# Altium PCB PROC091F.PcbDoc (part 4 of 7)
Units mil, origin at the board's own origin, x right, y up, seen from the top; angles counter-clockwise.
Board outline 3590.95 x 906.17 mil, 8 copper layers (Top Layer, GND1, Sig1, PWR1, PWR2, Sig2, GND2, Bottom Layer), stack 63.146 mil thick; 420 components, 316 nets, 1432 pads, 774 vias.
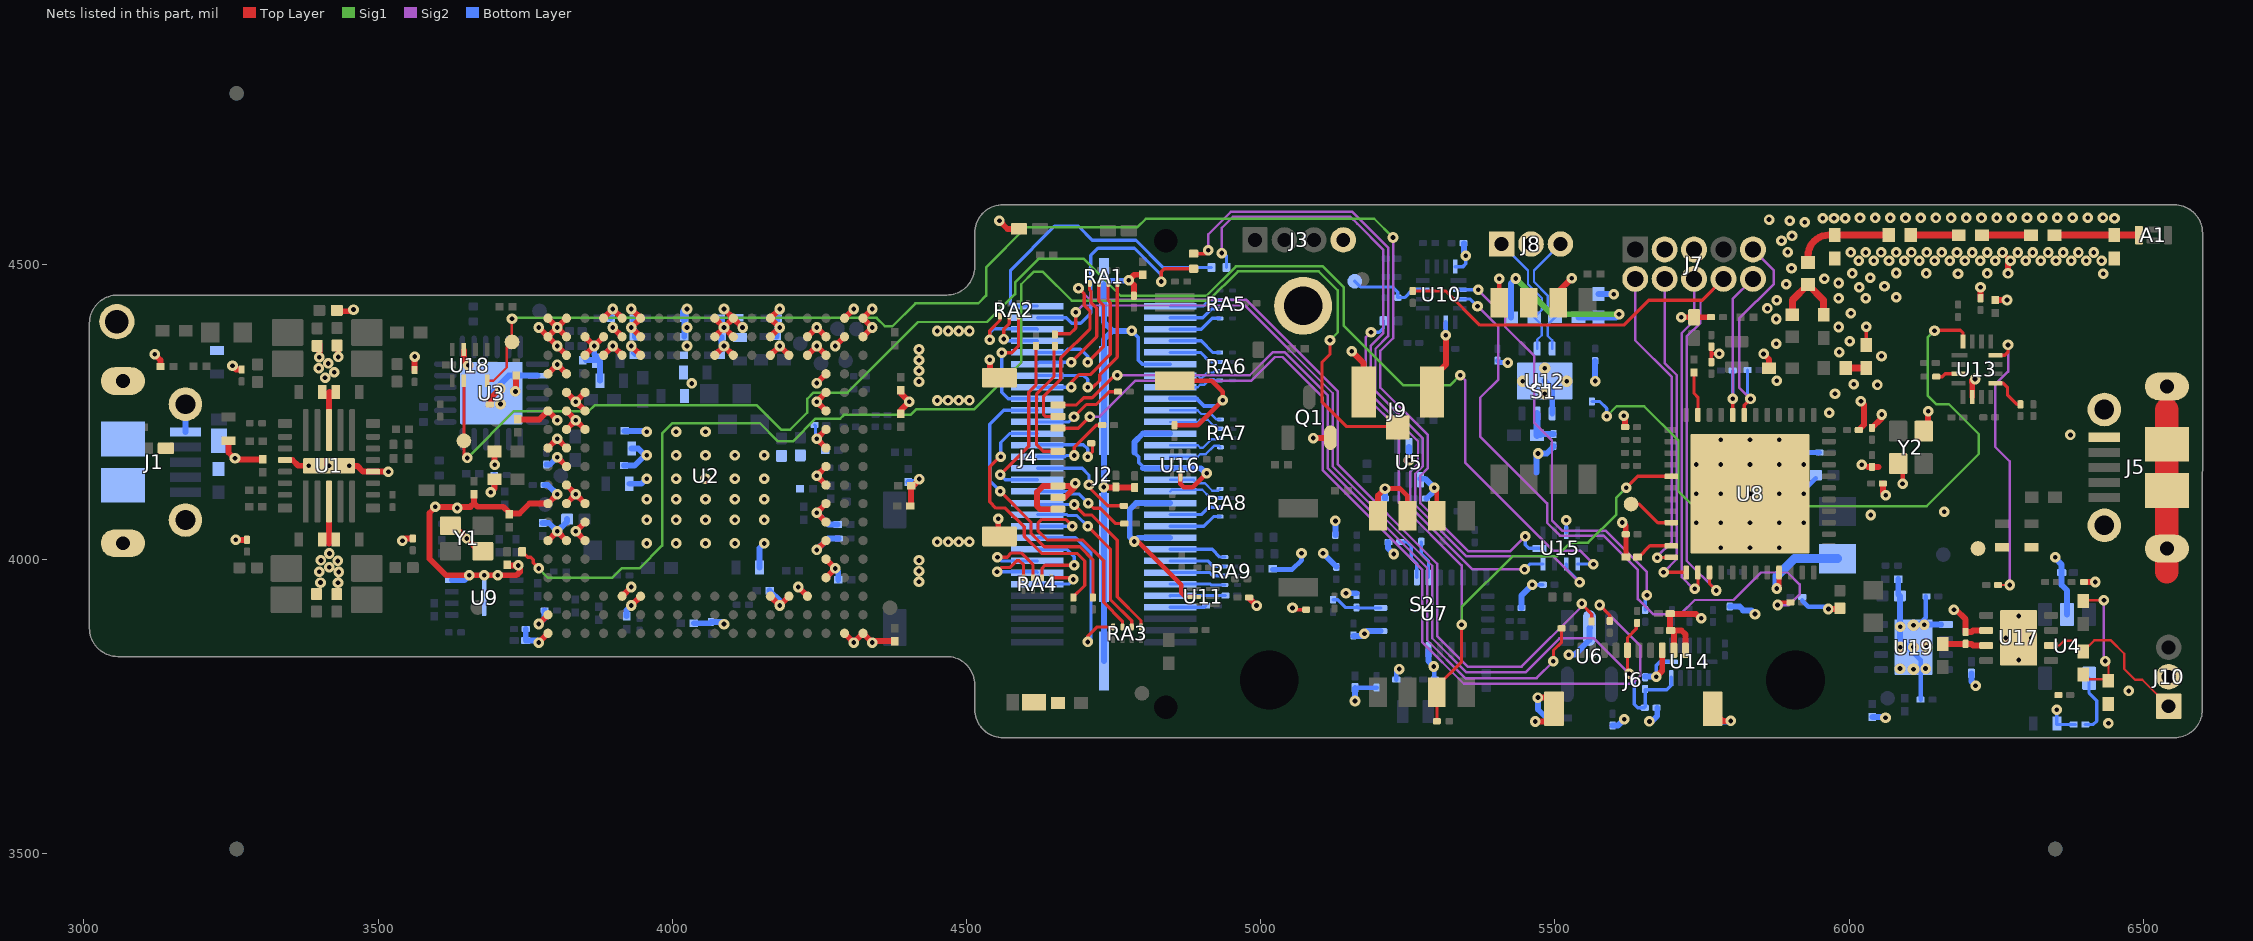
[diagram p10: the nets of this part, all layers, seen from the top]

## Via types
v1: diameter 18, hole 8, Top Layer to Bottom Layer, tented both sides, 737 vias
v2: diameter 19.68, hole 7.87, Top Layer to Bottom Layer, tented both sides, 36 vias
v3: diameter 17, hole 8, Top Layer to Bottom Layer, tented both sides, 1 vias

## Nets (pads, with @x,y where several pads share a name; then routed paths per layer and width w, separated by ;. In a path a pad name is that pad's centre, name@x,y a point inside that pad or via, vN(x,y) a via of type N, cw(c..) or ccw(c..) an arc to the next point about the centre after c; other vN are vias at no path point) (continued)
BOOTN: R80.2 R96.1 U7.4 | length 89.9
  Bottom Layer w5.5: R80.2@5123,3931 5130.87,3931 5142.87,3919 5143,3919 ; 5142,3920 5143,3919 ; R96.1@5162.8,3917.57 5144.43,3917.57 5143,3919 ; R96.1@5162.8,3919 R96.1@5163.76,3919 ; R96.1@5165,3919 R96.1@5163.76,3919 ; U7.4@5203.84,3917.06 5165.69,3917.06 R96.1@5163.76,3919
BREAK_RS232RX: TP19.1 U15.6 U18.7 | length 2663.5
  Top Layer w5.5: U18.7@3645.95,4303.01 TP19.1@3645.95,4200.94 3645.95,4177.64 v1(3651.7,4171.89)
  Sig1 w4.2: v1(3651.7,4171.89) 3651.8,4171.89 3731.31,4251.4 3858.11,4251.4 3867.87,4261.15 4143.84,4261.15 4184.81,4220.18 4200.56,4220.18 4229.37,4248.99 4229.37,4272.16 4240.11,4282.89 4297.89,4282.89 4417.91,4402.91 4534.91,4402.91 4582.46,4450.46 4582.46,4470.35 4622.27,4510.16 4699.37,4510.16 4761.92,4447.6 4908.02,4447.6 4957.82,4497.4 5105.6,4497.4 5141.34,4461.66 5141.34,4396.41 5242.09,4295.66 5322.29,4295.66 v1(5339,4312.38)
  Sig2 w4.2: v1(5339,4312.38) 5347.73,4303.65 5347.73,4248.79 ; 5347.71,4215.22 5347.71,4248.78 ; 5347.73,4215.21 5347.73,4163.41 5496.63,4014.5 5542.33,4014.5 v1(5565.37,3991.46)
  Bottom Layer w5.5: U15.6@5538.73,3991.77 5539.04,3991.46 v1(5565.37,3991.46)
BREAK_RS232TX: TP18.1 U15.10 U18.9 | length 2513.4
  Top Layer w4.2: U18.9@3685.32,4303.01 3695.92,4303.01 3718.72,4325.81 3718.72,4360.18 TP18.1@3727.56,4369.01 v1@3727.56,4409.77
  Sig1 w4.2: v1@3727.56,4409.77 4347.13,4409.77 4361.3,4395.61 4373.97,4395.61 4413.02,4434.66 4519.99,4434.66 4533.24,4447.91 4533.24,4495.82 4601.57,4564.15 4790.54,4564.15 4804.73,4578.34 5192.99,4578.34 v1(5224.85,4546.48)
  Sig2 w4.2: v1(5224.85,4546.48) 5224.85,4375.38 5203.48,4354.01 5203.48,4291.19 5284.08,4210.6 5284.08,4154.51 5271.03,4141.47 5271.03,4095.28 5353.32,4012.99 5423.87,4012.99 v1(5449.37,4038.49)
  Bottom Layer w5.5: v1(5449.37,4038.49) 5449.37,4024.34 5455.37,4018.34 U15.10@5473.77,4018.34
  other v1: 3727.56,4408.57
"BT ENABLE": R30.1 R110.1 S2.3 U8.17 | length 1280.9
  Top Layer w5.5: R110.1@5299.37,3724.46 S2.3@5299.37,3773.46 5299.37,3783.46 5341.37,3825.46 v1(5341.37,3888.46) ; v1(5621,4121) 5640.64,4140.64 U8.17@5697.71,4140.64
  Sig1 w4.2: v1(5341.37,3888.46) 5341.37,3918.37 5427.68,4004.68 5502.99,4004.68 5526.3,4028 5556.37,4028 5604.37,4076 5604.37,4104.37 v1(5621,4121)
  Sig2 w4.2: v1(5187.37,4385.46) 5178.28,4376.37 5178.28,4276.72 5234.87,4220.13 5234.87,4095.8 5341.37,3989.3 v1(5341.37,3888.46)
  Bottom Layer w5.5: v1(5187.37,4385.46) 5201.11,4385.46 5208.7,4393.06 R30.1@5208.7,4404.87
BT_RST: R91.2 U10.3 | length 1123.3
  Top Layer w5.5: v1(5878.37,3921.94) 5882.89,3926.46 R91.2@5900.13,3926.46
  Sig2 w4.2: v1(5368.37,4429.85) 5403.87,4394.36 5403.87,4305.15 5372.93,4274.2 5372.93,4238.35 ; 5372.91,4225.66 5372.91,4238.34 ; 5372.93,4225.65 5372.93,4208.47 5486.6,4094.79 5486.6,4061.8 5508.4,4040 5582.47,4040 5641.07,3981.4 5641.07,3932.13 5666.73,3906.46 5713.69,3906.46 5737.69,3930.46 5803.46,3930.46 5850.2,3977.2 5895.63,3977.2 5915.77,3957.07 5915.77,3939.99 5897.72,3921.94 v1(5878.37,3921.94)
  Bottom Layer w5.5: U10.3@5338.3,4441.85 5356.37,4441.85 v1(5368.37,4429.85)
BT_UART_RX: J7.9 R90.2 U8.7 | length 384
  Top Layer w5.5: U8.7@5821.73,4244.97 5821.76,4245 5821.76,4261.53 v1(5832.37,4272.14)
  Sig2 w4.2: v1(5832.37,4272.14) 5813,4291.51 5813,4408.67 5872,4467.67 5872,4490.65 J7.9@5836.47,4526.19
  Bottom Layer w5.5: R90.2@5827.38,4321.29 5827.38,4277.13 v1(5832.37,4272.14)
BT_UART_TX: J7.10 R102.2 U8.8 | length 293.4
  Top Layer w5.5: U8.8@5802.04,4244.97 v1(5802.04,4272.45)
  Sig2 w4.2: v1(5802.04,4272.45) 5802.04,4441.76 J7.10@5836.47,4476.19
  Bottom Layer w5.5: v1(5802.04,4272.45) R102.2@5802.04,4320.41
CAN1_FD_RX: R127.2 U13.3 | length 39.7
  Top Layer w5.5: R127.2@6148,4310 6158.12,4310 6163,4314.88 U13.3@6185.63,4314.88
CAN1_FD_TX: R123.2 U13.16 | length 1168.2
  Top Layer w5.5: v1(6145,4388) 6146,4389 6189,4389 6193.5,4384.5 U13.16@6193.5,4370
  Sig1 w4.2: v1(5588,4242.75) 5604.92,4259.66 5651.61,4259.66 5710,4201.27 5710,4115 5735,4090 5992.27,4090 5992.45,4090.18 6131.82,4090.18 6220.3,4178.66 6220.3,4212.34 6169.34,4263.3 6147.7,4263.3 6133.3,4277.7 6133.3,4376.3 v1(6145,4388)
  Bottom Layer w5.5: R123.2@5563,4267.77 5576.23,4267.77 5588,4256 v1(5588,4242.75)
CAN2_FD_RX: R120.2 U13.9 | length 65
  Top Layer w5.5: U13.9@6248.62,4299.13 6262,4299.13 6269,4292.13 6269,4279.1 6285.1,4263 R120.2@6291,4263
CAN2_FD_TX: R116.2 U13.12 | length 483.1
  Top Layer w4: R116.2@6252.99,3956 v1(6272.97,3956)
  Top Layer w5.5: U13.12@6248.62,4346.38 6264.28,4346.38 6270,4352.1 v1(6270,4364)
  Sig2 w4.2: v1(6270,4364) 6270,4318.7 6248,4296.7 6248,4191 6272.97,4166.03 v1(6272.97,3956)
CLKSEL0: R82.2 U7.10 | length 65.5
  Bottom Layer w5.5: R82.2@5272.85,4029.17 5272.85,4009.38 5285.04,3997.19 U7.10@5285.04,3968.74
CONN_AR_RS232RX: R14.2 U15.7 | length 1259.6
  Top Layer w5.5: R14.2@4886,4519.05 4906.72,4519.05 v1@4911,4523.33
  Sig2 w4.2: v1(4911,4525) 4911,4551.96 4949.04,4590 5155.96,4590 5216.44,4529.52 5216.44,4378.86 5195.08,4357.49 5195.08,4285.49 5275.68,4204.89 5275.68,4157.99 5262.63,4144.95 5262.63,4091.8 5349.84,4004.59 5497.75,4004.59 v1(5541.83,3960.5)
  Bottom Layer w5.5: U15.7@5519.05,3991.77 5519.05,3983.29 v1(5541.83,3960.5)
CONN_AR_RS232TX: R12.2 U15.9 | length 1135.8
  Sig2 w4.2: v1(4934,4520) 4934,4563.08 4952.46,4581.54 5152.55,4581.54 5164.08,4570 5208.05,4526.04 5208.05,4383.58 5186.68,4362.22 5186.68,4280.81 5267.28,4200.22 5267.28,4161.47 5254.23,4148.43 5254.23,4088.32 5360.12,3982.44 v1(5448.37,3982.44)
  Bottom Layer w5.5: v1(4934,4520) 4936.91,4520 4941.96,4514.95 R12.2@4941.96,4495.46 ; v1(5448.37,3982.44) 5457.7,3991.77 U15.9@5479.68,3991.77
DCDC_SW: L7.1 U8.33 | length 165.6
  Top Layer w8: v1(5876.87,3950) 5880.78,3953.91 U8.33@5880.78,3977.25
  Bottom Layer w15: v1(5876.87,3950) 5876.87,3971.1 5906.6,4000.83 L7.1@5980.15,4000.83
DIO6_GLED: R17.1 U8.11 | length 74.9
  Top Layer w5.5: R17.1@5736.37,4317.15 5736.37,4281.63 5742.99,4275.01 U8.11@5742.99,4244.97
DISP: R168.2 U10.2 | length 739.6
  Sig2 w4.2: v1(5369.57,4457.6) 5415.3,4411.87 5415.3,4394.81 5465,4345.11 5465,4231.46 5495,4201.46 5495,4065.5 5512.1,4048.4 5585.95,4048.4 5656.37,3977.98 v1(5656.37,3938.46)
  Bottom Layer w5.5: U10.2@5337.31,4457.6 v1(5369.57,4457.6) ; R168.2@5653.43,3913.58 5653.43,3935.52 v1(5656.37,3938.46)
DISP_T: C114.2 J6.5 R180.2 R181.1 R182.1 U14.5 | length 1724.1
  Top Layer w5.5: R182.1@4650.14,4382.85 4675.87,4382.85 4685.68,4392.66 v1(4685.68,4419.55) ; v1(5626.13,3805.38) 5623.32,3808.19 J6.5@5623.32,3845.06 5623.32,3866.63 5638.29,3881.6 R181.1@5638.29,3890.63
  Sig2 w4.2: v1(4685.68,4419.55) 4697.08,4430.95 4973.3,4430.95 5122.43,4281.83 5122.43,4157.66 5291.47,3988.61 5291.47,3865.5 5349.4,3807.57 5449.92,3807.57 5507.5,3865.15 5566.37,3865.15 v1(5626.13,3805.38)
  Bottom Layer w5.5: v1(5626.13,3805.38) 5634.82,3796.69 5634.82,3753.22 5640.7,3747.34 5651.73,3747.34 5653.37,3748.99 5653.37,3778.13 5690.11,3778.13 5697.73,3785.75 U14.5@5697.73,3797.8 U14.5@5697.73,3799.77
GND: C1.1 C2.1 C3.1 C4.2 C5.2 C6.1 C7.2 C8.2 C9.1 C10.1 C11.2 C12.1 C13.1 C14.1 C15.2 C16.2 C17.2 C18.2 C19.2 C20.2 C21.1 C23.2 C24.2 C25.2 C26.2 C27.2 C28.2 C29.2 C30.2 C31.2 C32.2 C33.2 C34.2 C35.2 C36.2 C37.2 C38.2 C39.2 C40.2 C41.2 C42.1 C43.1 C44.2 C45.2 C46.2 C47.2 C48.2 C49.2 C50.2 C51.2 C52.2 C53.2 C54.2 C55.2 C56.2 C57.2 C58.2 C59.2 C60.2 C61.2 C62.2 C63.2 C64.2 C65.2 C66.2 C67.2 C68.2 C69.2 C70.2 C71.1 C72.1 C73.2 C74.2 C75.2 C76.2 C77.2 C78.2 C79.2 C80.2 C81.2 C82.2 C83.2 C84.2 C85.2 C86.2 C87.2 C88.2 C89.2 C90.2 C91.2 C92.2 C94.2 C95.2 C96.2 C97.2 C98.2 C100.2 C101.2 C102.2 C103.2 C104.2 C105.1 C106.1 C107.2 C108.1 C109.1 C110.1 C114.1 C115.2 C116.2 C117.2 C118.2 C119.2 C120.2 C122.2 C123.2 C125.2 C126.2 C127.2 C128.2 C129.2 C130.2 J1.5 J1.6 J1.7 J1.8 J1.9 J1.10 J1.11 J2.20 J2.26 J2.32 J2.38 J2.44 J2.50 J2.MP1 J2.MP2 J2.MP3 J2.MP4 J3.4 J4.8 J4.9 J4.10 J4.11 J4.12 J5.5 J5.6 J5.7 J5.8 J5.9 J5.10 J5.11 J6.8 J6.9 J6.10 J6.11 J6.12 J7.3 J7.5 J8.2 J9.2@5174.89,4283.6 J9.3@5291.03,4283.6 J10.2 LD1.2 LD2.2 LD6.2 Q1.2 R3.2 R15.1 R24.1 R29.1 R37.1 R42.2 R52.1 R65.1 R69.1 R73.1 R92.2 R93.2 R96.2 R98.2 R122.2 R125.1 R134.2 R141.2 R158.1 R170.1 R172.1 R180.1 S1.6 S1.7 S1.8 S2.6 S2.7 S2.8 SW2.2 TP12.1 TP15.1 TP20.1 U1.4 U1.11 U1.17 U1.24 U1.27 U2.A1 U2.A2 U2.A6 U2.A8 U2.A11 U2.A13 U2.A15 U2.A17 U2.A18 U2.B6 U2.B8 U2.B9 U2.B10 U2.B11 U2.B12 U2.B13 U2.B14 U2.B15 U2.B16 U2.B17 U2.B18 U2.C6 U2.C7 U2.C8 U2.C12 U2.C13 U2.C14 U2.C16 U2.C17 U2.D16 U2.D17 U2.D18 U2.E3 U2.E16 U2.E17 U2.E18 U2.F3 U2.F16 U2.F17 U2.F18 U2.K16 U2.K17 U2.K18 U2.L16 U2.L17 U2.L18 U2.N3 U2.N16 U2.N17 U2.N18 U2.P3 U2.P16 U2.R3 U2.R16 U2.R17 U2.T4 U2.T5 U2.T6 U2.T7 U2.T8 U2.T9 U2.T10 U2.T11 U2.T12 U2.T13 U2.T14 U2.T15 U2.T16 U2.T17 U2.U1 U2.U17 U2.U18 U2.V1 U2.V17 U2.V18 U3.2 U3.25 U4.2 U5.2 U5.4 U6.2 U7.2 U7.25 U8.49 U9.4 U9.9 U10.6 U10.16 U11.2 U12.2 U12.9@5482.58,4302.51 U13.6 U14.6 U15.3 U16.2 U17.2 U17.9@6287.97,3866 U18.3 U19.5 U19.9@6109.37,3850.46 Y1.2 Y1.4 Y2.2 Y2.4 | length 10328
  Top Layer w5.5: C40.2@4980.39,3933.61 C40.2@4980.39,3934.38 ; v1(5054,3917) 5056.96,3914.04 R125.1@5077.13,3914.04 ; C20.2@5765.79,4334.83 5765.79,4349 ; C19.2@5765.79,4361.03 5765.79,4349 ; v1(5779,4348.8) 5778.8,4349 5765.79,4349 ; C21.1@6028.92,4363.78 v1(6028.92,4395.08) ; v1@6223,4462 v1(6223.22,4461.78) ; v1(6268.28,4440.28) v1@6269,4441
  Top Layer w8: v1(4785.33,4029.82) 4791.76,4029.82 4865.14,3956.44 4865.14,3943.16 4872.16,3936.15 4886.95,3936.15 U11.2@4886.95,3935.72 ; C72.1@4853.37,4227.49 4893.14,4227.49 v1(4935.65,4270) 4935.65,4284.18 4916.82,4303.01 SW2.2@4854.16,4303.01 ; U16.2@4863.37,4143.71 4863.37,4127.78 4869.25,4121.9 4884.53,4121.9 v1(4908.49,4145.87) ; v1(5211.17,4119.83) 5236.79,4119.83 5249.16,4107.46 5249.16,4073.68 S2.7@5249.37,4073.46 ; v1(5294.73,4121.32) 5299.37,4116.68 S2.6@5299.37,4073.46 ; S1.8@5405.37,4435.46 v1(5405.37,4476.19) ; C26.2@5620.36,4042.21 5620.64,4041.92 C24.2@5620.64,4003.46 ; v1(6090.77,4128.23) 6090.91,4128.38 Y2.2@6090.91,4162.29 ; v1@6158.96,4082.88 v1(6161.37,4080.46) v1@6162.37,4081.46
  Top Layer w10: v1(3120.4,4348.11) 3130.38,4338.13 R52.1@3130.38,4327.36 ; C1.1@3245.8,4201.22 3245.8,4181.13 v1@3254.84,4172.09 ; v1(3252.64,4328.46) 3252.64,4327.94 3258.45,4322.12 C32.2@3267.13,4322.12 ; v1(3256.91,4171.34) 3258.71,4169.54 C30.2@3304,4169.54 ; v1(3258.02,4032.76) C34.2@3277.23,4032.76 ; U1.17@3341.81,4168.36 3354.6,4168.36 3364.41,4158.56 3372.36,4158.56 ; v1@3399.92,4344.56 v1@3400.21,4344.85 ; v1@3400.21,4343.85 v1@3400.21,4344.85 ; C45.2@3400.21,4363.56 v1@3400.21,4344.85 ; C45.2@3400.21,4364.56 C45.2@3400.5,4364.85 ; U1.24@3416.61,4097.89 3416.61,4026.67 3416.67,4026.6 ; v2(3416.61,4158.52) v2(3450.86,4158.52) 3464.72,4158.52 3474.56,4148.68 U1.4@3491.41,4148.68 3517.45,4148.68 v1(3517.61,4148.52) ; U1.11@3416.61,4219.15 3416.61,4283.53 3417.5,4284.42 ; C77.2@3429.9,4421.17 3455.37,4421.17 v1(3458.2,4424) ; v1@3432.13,4345.03 v1@3432.43,4345.32 ; v1@3432.43,4344.32 v1@3432.43,4345.32 ; C44.2@3432.43,4364.04 v1@3432.43,4345.32 ; C44.2@3432.43,4365.04 C44.2@3432.72,4365.33 ; v1(3541.4,4031) 3545.52,4035.11 C33.2@3559.04,4035.11 ; C31.2@3562.13,4321.23 3562.13,4343.87 v1(3562.47,4344.2) ; Y1.4@3622.98,4056.69 3628.88,4056.69 v3(3650.54,4035.03) 3672.19,4013.38 Y1.2@3678.09,4013.38 ; Y1.4@3623.17,4054.18 Y1.4@3629.39,4054.18 ; U18.3@3645.95,4354.59 3645.95,4336.82 v1(3653.37,4329.4) ; R15.1@3663,4110.46 3663,4095 ; Y1.2@3672.7,4010.87 Y1.2@3678.28,4010.87 ; C126.2@3690.95,4262.91 3690.95,4273.3 v1(3707.55,4289.9) ; v1(3691.74,4113.6) 3697.82,4119.68 C89.2@3697.82,4135.45 ; C90.2@3697.69,4182.85 3697.69,4160.66 v1@3697.82,4160.53 ; C14.1@3724.34,3990.34 3725.45,3989.23 v1(3738.48,3989.23) 3741.28,3989.23 3741.28,3978.28 3735.46,3972.46 v1(3703.21,3972.46) v1(3655,3972.46) 3615.61,3972.46 3587.57,4000.5 3587.57,4078.41 3597.96,4088.8 3656.8,4088.8 3663,4095 ; v1(3733.44,4284.91) 3734.67,4286.14 C69.2@3734.67,4311.95 ; C63.2@3737.19,4237.51 3774.43,4237.51 U2.A13@3788.76,4251.85 v1(3804.51,4236.1) ; v1(3773.02,3858.15) U2.A1@3788.76,3873.89 ; v1(3773.02,3889.64) U2.A2@3788.76,3905.39 ; v1(3773.02,4393.58) U2.A17@3788.76,4377.83 ; U2.A6@3788.76,4031.37 v1(3804.51,4047.12) U2.B6@3820.26,4031.37 ; U2.A11@3788.76,4188.85 v1(3804.51,4204.6) U2.B11@3820.26,4188.85 ; U2.A15@3788.76,4314.84 v1(3804.51,4330.59) U2.B15@3820.26,4314.84 ; U2.A18@3788.76,4409.33 v1(3804.51,4393.58) ; v1(3804.51,4110.11) U2.A8@3788.76,4094.37 3757.27,4094.37 3740.54,4077.64 3724.16,4077.64 3724.16,4077.57 C71.1@3722.86,4076.27 3722.86,4079.14 3713,4089 3669,4089 3663,4095 ; v1(3804.51,4173.11) U2.B10@3820.26,4157.36 ; U2.B8@3820.26,4094.37 v1(3836.01,4110.11) ; U2.B9@3820.26,4125.86 v1(3836.01,4110.11) ; U2.B12@3820.26,4220.35 v1(3836.01,4236.1) ; U2.B13@3820.26,4251.85 v1(3836.01,4236.1) ; U2.B14@3820.26,4283.34 v1(3836.01,4267.59) ; U2.B16@3820.26,4346.33 v1(3804.51,4362.08) U2.A17@3788.76,4377.83 ; U2.B17@3820.26,4377.83 v1(3804.51,4393.58) ; U2.B18@3820.26,4409.33 v1(3804.51,4393.58) ; U2.C6@3851.76,4031.37 v1(3836.01,4047.12) U2.C7@3851.76,4062.87 ; U2.C8@3851.76,4094.37 v1(3836.01,4110.11) ; U2.C12@3851.76,4220.35 v1(3836.01,4236.1) ; U2.C13@3851.76,4251.85 v1(3836.01,4267.59) ; U2.C14@3851.76,4283.34 v1(3836.01,4267.59) ; U2.C16@3851.76,4346.33 v1(3867.5,4362.08) ; U2.C17@3851.76,4377.83 v1(3867.5,4362.08) ; U2.D16@3883.25,4346.33 v1(3899,4362.08) U2.E16@3914.75,4346.33 ; U2.D17@3883.25,4377.83 v1(3867.5,4362.08) ; U2.D18@3883.25,4409.33 v1(3899,4425.07) U2.E18@3914.75,4409.33 ; v1(3899,4393.58) U2.E17@3914.75,4377.83 ; U2.E3@3914.75,3936.89 v1(3930.5,3952.63) ; v1(3930.5,3921.14) U2.F3@3946.24,3936.89 ; v1(3930.5,4362.08) U2.F16@3946.24,4346.33 ; v1(3930.5,4425.07) U2.F18@3946.24,4409.33 v1(3930.5,4393.58) U2.F17@3946.24,4377.83 ; U2.K16@4072.23,4346.33 v1(4087.98,4362.08) U2.L16@4103.72,4346.33 ; U2.K17@4072.23,4377.83 v1(4087.98,4393.58) ; U2.K18@4072.23,4409.33 v1(4087.98,4393.58) ; v1(4087.98,4425.07) U2.L18@4103.72,4409.33 ; U2.L17@4103.72,4377.83 v1(4087.98,4393.58) ; v1(4119.47,4393.58) U2.L18@4103.72,4409.33 ; U2.N3@4166.72,3936.89 v1(4182.46,3921.14) U2.P3@4198.21,3936.89 ; U2.N16@4166.72,4346.33 v1(4182.46,4362.08) U2.P16@4198.21,4346.33 ; U2.N17@4166.72,4377.83 v1(4182.46,4393.58) U2.N18@4166.72,4409.33 v1(4182.46,4425.07) ; v1(4213.96,3952.63) U2.R3@4229.71,3936.89 ; U2.R16@4229.71,4346.33 v1(4245.46,4362.08) U2.T16@4261.2,4346.33 ; U2.R17@4229.71,4377.83 v1(4245.46,4393.58) U2.T17@4261.2,4377.83 ; v1(4245.46,4015.63) U2.T6@4261.2,4031.37 ; v1(4245.46,4299.09) U2.T15@4261.2,4314.84 ; U2.T4@4261.2,3968.38 v1(4276.95,3984.13) U2.T5@4261.2,3999.88 ; U2.T7@4261.2,4062.87 v1(4245.46,4078.62) U2.T8@4261.2,4094.37 ; U2.T9@4261.2,4125.86 v1(4245.46,4141.61) U2.T10@4261.2,4157.36 ; U2.T11@4261.2,4188.85 v1(4245.46,4204.6) U2.T12@4261.2,4220.35 ; U2.T13@4261.2,4251.85 v1(4245.46,4267.59) U2.T14@4261.2,4283.34 ; v1(4276.95,4362.08) U2.U17@4292.7,4377.83 ; U2.U1@4292.7,3873.89 v1(4308.45,3858.15) U2.V1@4324.2,3873.89 v1(4339.94,3858.15) 4342.43,3860.63 C60.2@4378.33,3860.63 ; U2.U18@4292.7,4409.33 v1(4308.45,4425.07) ; U2.V17@4324.2,4377.83 v1(4339.94,4393.58) U2.V18@4324.2,4409.33 v1(4339.94,4425.07) ; C96.2@4388.37,4246.78 4388.37,4252.87 v1(4402.94,4267.44) 4388.37,4282.01 C98.2@4388.37,4286.73 ; C102.2@4405.36,4090.24 4405.93,4090.82 C88.2@4405.93,4124.76 4409.76,4124.76 v1@4421,4136 ; v1(4539.65,4338.94) 4539.65,4317.15 4548.63,4308.18 J4.11@4554.03,4308.18 ; J4.12@4554.03,4038.49 v1(4554.03,4068.8) ; v1(4555.92,4574.89) 4569.75,4561.07 LD2.2@4589.4,4561.07 ; J4.10@4655.33,4084.75 4625.21,4084.75 4619.91,4090.06 4619.91,4113.73 4630.3,4124.12 4680.13,4124.12 v1(4684.89,4128.88) 4684.89,4122.77 4666.56,4104.44 J4.9@4655.33,4104.44 ; v1(4733.36,4122.4) 4734.36,4121.4 4785.08,4121.4 C15.2@4785.89,4120.59 ; C120.2@4784.37,4447.48 4784.37,4465.69 v1(4775.99,4474.07) 4785.12,4483.2 R42.2@4799.25,4483.2 ; C40.2@4980.39,3933.61 v1(4993,3921) ; v1(5089.21,4205.68) 5117.78,4205.68 Q1.2@5118.39,4206.3 ; v1(5154.58,4353) 5174.89,4332.69 J9.2@5174.89,4283.6 ; S2.8@5199.37,4073.46 5199.37,4108.03 v1(5211.17,4119.83) ; J9.3@5291.03,4283.6 5291.03,4306.87 5314.67,4330.52 v1(5314.67,4380.2) ; v1(5466.64,3724.08) 5491.87,3724.08 5498.32,3730.54 5498.32,3756.69 5490.34,3764.68 v1(5471.07,3764.68) ; S1.6@5505.37,4435.46 5505.37,4454.46 v1(5528.37,4477.46) ; v1@5615.36,4062.2 5620.36,4057.2 C26.2@5620.36,4042.21 ; v1(5617.05,4243.42) 5617.05,4241.67 5619.36,4239.36 C25.2@5619.36,4224.38 ; v1(5672.33,3800.17) 5682.38,3810.22 J6.8@5682.38,3845.06 ; J6.9@5702.06,3842.06 C116.2@5702.06,3874.39 ; v1(5714.87,4411.08) LD6.2@5736.37,4411.08 C37.2@5765.37,4411.08 ; J6.10@5721.75,3845.06 5721.75,3872.09 5715.09,3878.74 C116.2@5696.56,3878.74 5695.85,3879.45 C115.2@5695.85,3907.2 5696.59,3906.46 5739.58,3906.46 5746.58,3899.46 v1(5748.74,3899.46) ; J6.12@5774.81,3767.91 5768.01,3761.12 5768.01,3742.65 5785.66,3725 v1(5798.82,3725) ; v1(5854.59,4348.67) 5863.91,4339.35 C23.2@5863.91,4324.42 ; v1@5964.75,3914.88 5976.37,3914.88 5981.02,3919.54 C28.2@5984.12,3916.44 ; C36.2@6016.45,4219.38 6025.38,4228.31 6025.38,4262.62 v1(6020,4268) ; 6032.1,4156.74 C18.2@6038.8,4156.74 6049.57,4156.74 ; C17.2@6038.8,4222.96 6055.37,4239.52 v1(6055.37,4245.75) ; C27.2@6057.38,4128.46 6057.38,4113.48 v1(6062.38,4108.48) ; Y2.4@6134.22,4217.41 6134.3,4217.48 6134.3,4251.39 v1(6134.37,4251.46) ; v1(6178,3914) 6181.58,3914 6197.97,3897.62 C108.1@6197.97,3876.02 ; C108.1@6197.97,3876.02 6207.97,3876 6210.76,3878.8 U17.2@6232.85,3878.8 ; U13.6@6209.25,4275.51 v1@6209.25,4299.75 ; C107.2@6223.22,4443.23 v1(6223.22,4461.78) ; R141.2@6248.22,4440.28 v1(6268.28,4440.28) ; v1(6269.98,4485.46) v1@6269.98,4511.09 ; R134.2@6399,3961 v1(6417.97,3961) ; v1@6474.69,3776.31 v1(6475,3776) ; U2.A17@3788.76,4377.83 v1(3804.51,4393.58) ; v1(4087.98,4393.58) U2.L18@4103.72,4409.33 ; v1@6209.25,4299.75 6209.25,4304.25 6209,4304 6209,4300 v1@6209.25,4299.75
  Top Layer w40: 6540,3978.57 J5.6@6540,4017.94 6540,4041.56 J5.7@6540,4116.36 J5.8@6540,4195.1 6540,4254.16
  Bottom Layer w5.5: v1(3930.5,4362.08) 3932.89,4359.69 3932.89,4349.72 C74.2@3936.37,4346.23 ; C57.2@4179.44,4409.4 4180.95,4410.91 4180.95,4423.56 v1(4182.46,4425.07) ; C130.2@4241.68,4228 4243.57,4226.11 4243.57,4206.49 v1(4245.46,4204.6) 4257.65,4192.4 4257.65,4187.6 C61.2@4259.95,4185.3 ; C6.1@5211,4103.02 C6.1@5211.17,4103.18 ; v1(5461.4,3956.46) C123.2@5479.37,3956.46 ; U15.3@5519.05,4044.92 v1(5519.05,4066.14) ; C106.1@5574,4450.19 C106.1@5574.31,4450.51 ; v1(6352.97,3744.15) C7.2@6352.97,3720.79 6352.97,3718.79 6384.16,3718.79 C8.2@6384.37,3719.01
  Bottom Layer w6: v1(4780.88,4387.88) 4792.16,4376.6 4792.16,4337.77 4798.42,4331.51 J2.50@4846.16,4331.51 ; 4785.32,4181.08 4792.37,4174.03 4792.37,4164.78 4800.11,4157.04 4800.11,4154.34 ; U10.16@5330.42,4496.49 5342.97,4496.49 5348.5,4502.02 v1(5348.5,4515.71) ; v1(5672.33,3800.17) 5672.33,3819.17 5678.53,3825.36 U14.6@5697.73,3825.36
  Bottom Layer w7: J2.44@4846.16,4272.63 4891.24,4272.63 4903.66,4260.22 4925.86,4260.22 v1(4935.65,4270)
  Bottom Layer w8: R37.1@5019.38,3982.46 5053.74,3982.46 5069.37,3998.09 v1(5069.37,4009.96) ; C11.2@5160.25,3781.63 5160.29,3781.59 5197.06,3781.59 C9.1@5197.1,3781.54 ; C38.2@5230.57,3795.13 5230.37,3795.33 5230.37,3808.06 v1(5235.37,3813.06) ; v1(5294.12,3817.45) 5295.06,3816.51 5295.06,3796.24 C39.2@5296.01,3795.3 ; v1(5314.67,4380.2) U10.6@5314.67,4402.48 ; C105.1@5402.37,4337.36 5405.79,4333.94 v1(5419.81,4333.94) ; 5920.49,3929.46 5930.82,3919.14 5960.8,3919.14 v1(5964.75,3915.18) ; v2(5923.1,4111.11) 5923.1,4117.1 C29.2@5943.47,4137.46 ; v2@5923.35,4160.46 v2(5923.1,4160.71) 5923.1,4172.87 5931.49,4181.25 C35.2@5949.53,4181.25 C35.2@5948.36,4180.08 ; U19.9@6099.37,3850.46 6121.45,3828.38 C128.2@6121.45,3761.12 ; U19.9@6118.62,3888.85 6130.36,3900.59 C127.2@6130.36,3936.75
  Bottom Layer w10: J1.5@3172.66,4215.96 J1.10@3172.66,4263.2 ; U9.4@3625.17,3964.2 3646.74,3964.2 v1(3655,3972.46) ; v1(3691.74,4113.6) 3697.53,4119.4 R65.1@3697.53,4143.04 ; U3.25@3692.64,4282.2 3722.17,4311.72 U3.2@3770.97,4311.72 ; C101.2@3751.01,3881.17 3751.01,3861.79 C100.2@3751.11,3861.69 3769.47,3861.69 v1(3773.02,3858.15) ; v1(3773.02,3889.64) 3783.12,3899.74 R3.2@3783.12,3912.76 ; C97.2@3779.79,4061.22 3790.41,4061.22 v1(3804.51,4047.12) 3821.32,4063.93 C48.2@3821.32,4067.82 ; C3.1@3782.96,4125.72 3788.9,4125.72 v1(3804.51,4110.11) ; C2.1@3785.88,4160.73 3792.14,4160.73 v1(3804.51,4173.11) ; C67.2@3853,4338.02 3874.98,4338.02 C70.2@3876,4337 ; v1(3867.5,4362.08) 3867.5,4347.58 C70.2@3876,4339.08 ; C73.2@3877,4303 3877,4336 C70.2@3876,4337 ; C68.2@3895.39,4409.24 3895.39,4421.47 v1(3899,4425.07) ; v1(3899,4362.08) C70.2@3876,4339.08 ; C64.2@3918.02,4159 3936,4159 3953.61,4176.61 3942.22,4188 C65.2@3931,4188 ; C66.2@3919.05,4218 3955.09,4218 v1(3956.48,4216.61) ; C95.2@3922.37,3902.78 3922.37,3913.01 v1@3930.78,3921.43 ; C62.2@3927,4128 3947.87,4128 v1(3956.48,4136.61) ; C75.2@3934.43,4409.11 3934.35,4409.02 3934.35,4397.43 v1(3930.5,4393.58) 3936.37,4387.7 C76.2@3936.37,4377.73 ; C84.2@4020.26,4377.83 4020.26,4388.85 v1(4024.98,4393.58) 4020.26,4398.3 C85.2@4020.26,4409.33 ; C87.2@4036.64,3891.02 4063.65,3891.02 C92.2@4065.74,3893.11 4084.88,3893.11 v1@4088.4,3889.59 ; C80.2@4083.77,4377.76 4083.77,4366.29 v1(4087.98,4362.08) ; C81.2@4084.39,4409.24 4084.39,4397.16 v1(4087.98,4393.58) ; C59.2@4148.3,3985.94 4148.3,4018.43 v1(4156.48,4026.61) ; R170.1@4165.37,3946.46 4182.46,3929.37 v1(4182.46,3921.14) ; C56.2@4177.39,4378.24 4177.39,4388.51 v1(4182.46,4393.58) 4177.74,4398.3 C57.2@4177.74,4409.33 ; v1(4245.46,4015.63) 4265,4035.17 C91.2@4282.98,4035.17 ; v1@4245.46,4079.47 v1(4245.46,4078.62) 4265.27,4058.8 C103.2@4280.95,4058.8 ; v1(4276.95,3984.13) 4282.16,3978.92 C94.2@4282.16,3964.68 ; R172.1@4401.11,4131.01 4413.91,4131.01 v1@4421,4138.1 ; v1@4421,4136 v1@4421,4138.1 ; v1@4422.04,4139.14 v1@4421,4138.1 ; J2.MP1@4733.36,3826.98 J2.MP2@4733.36,4019.5 v1(4733.36,4122.4) J2.MP3@4733.36,4269.5 4733.36,4373.14 4748.1,4387.88 ; v1@4775.99,4473.07 4741.12,4473.07 4731.72,4463.66 J2.MP4@4733.36,4462.02 4733.36,4402.63 4748.1,4387.88 ; v1(4780.88,4387.88) 4748.1,4387.88 ; 4785.32,4181.08 4785.32,4198.61 4800.11,4213.4 J2.38@4846.16,4213.4 ; 4800.11,4154.34 J2.32@4846.16,4154.34 4898.01,4154.34 v1@4908.49,4143.87 ; J2.20@4846.16,4036.23 4791.73,4036.23 v1(4785.33,4029.82) 4777.36,4037.79 4777.36,4084.26 4788.39,4095.29 J2.26@4846.16,4095.29 ; v1(5105.98,4009.88) 5105.98,4009.76 R98.2@5128.47,3987.27 ; R93.2@5126.93,4041.1 v1(5126.93,4064.83) ; v1(5144.97,3942) R96.2@5162.8,3942 ; C10.1@5157.67,3869.37 5172.73,3869.37 v1(5176.24,3872.88) 5181.05,3877.69 U7.2@5203.84,3877.69 ; v1(5160.25,3758.88) C11.2@5160.25,3780.47 ; C6.1@5211.17,4103.18 v1(5211.17,4119.83) ; C13.1@5216.16,4028.9 5216.16,4018.53 v1(5226.01,4008.68) ; v1(5251.98,4167.81) U5.2@5251.98,4190.93 ; U5.4@5271.66,4136.6 5279.45,4136.6 v1(5294.73,4121.32) 5294.73,4115.77 C125.2@5281.86,4102.9 ; U7.25@5285.04,3845.7 5285.04,3826.53 v1(5294.12,3817.45) ; C117.2@5345.41,4536.81 5345.41,4521.23 5348.5,4518.15 v1(5348.5,4515.71) ; R73.1@5443.38,3917.06 5443.38,3938.44 v1(5461.4,3956.46) ; 5468.82,4146.92 5468.82,4176.91 v1(5471.37,4179.46) 5486.08,4179.46 5497.81,4191.2 C43.1@5497.81,4192.56 ; v1(5471.07,3764.68) 5471.07,3744.55 5485.66,3729.96 R69.1@5500.05,3729.96 ; U12.9@5482.58,4302.51 5495.37,4289.72 U12.2@5495.37,4247.39 ; v1(5523.37,3837.67) 5533.86,3837.67 5558.54,3862.35 U6.2@5558.54,3882.87 ; U6.2@5560.04,3882.87 U6.2@5560.04,3883.76 ; v1(5568.37,4302.51) R122.2@5568.37,4336.6 ; C106.1@5574,4450.19 5599.81,4450.19 v1(5600,4450) ; C12.1@5598.06,3717.04 5606.75,3717.04 v1(5617.59,3727.88) ; R180.1@5653.37,3800.17 v1(5672.33,3800.17) ; v1(5660.61,3724.14) 5664.73,3724.14 5673.78,3733.19 C114.1@5673.78,3747.34 ; C118.2@5760.69,3723.85 5791.91,3723.85 5793.05,3725 v1(5798.82,3725) ; C119.2@5797.1,3919.22 5814.11,3919.22 5819.79,3913.54 5819.79,3912.93 5833.66,3912.93 v1(5840,3906.59) ; R92.2@6039.37,3731.63 6060.41,3731.63 v1(6061.75,3730.29) ; R29.1@6083.39,3965.94 6083.39,3940.34 R24.1@6086.28,3937.46 6086.28,3863.56 U19.9@6099.37,3850.46 ; U19.9@6118.62,3888.85 U19.5@6156.46,3888.85 ; C129.2@6207.77,3805.87 6207.77,3791.85 v1(6214.88,3784.74) ; v1(6350,4003) 6350,4001.72 6361.13,3990.59 C5.2@6361.13,3977 6361.13,3955.87 6370.37,3946.63 U4.2@6370.37,3905.76 ; C70.2@3876,4337 C70.2@3876,4339.08
  Bottom Layer w15: C85.2@4020.26,4409.33 4020.26,4420.35 v1(4024.98,4425.07)
  other v1: 6440.6,3720.9 6086.39,3813.91 6129.87,3813.91 6109.37,3850.46 6086.92,3884.93 6127.76,3888.2 4087.98,3889.59 3402.25,3960.12 3431.87,3959.79 4419.27,3961.6 3680.37,3972.46 3433.16,3978.06 3400.29,3978.58 4419.27,3979.67 3416.85,3985.95 3431.28,3996.91 3402.96,3997.73 4419.21,3997.72 3417.4,4009.53 3956.48,4026.61 4006.48,4026.61 4056.48,4026.61 4106.48,4026.61 4450.49,4029.21 4468.83,4029.2 4486.89,4029.2 4504.94,4029.26 5614.47,4062.2 3956.48,4066.61 4006.48,4066.61 4056.48,4066.61 4106.48,4066.61 4156.48,4066.61 6036.85,4074.88 3634.65,4086.8 3596.96,4088.8 3956.48,4101.61 4006.48,4101.61 4056.48,4101.61 4106.48,4101.61 4156.48,4101.61 4419.8,4136 4006.48,4136.61 4056.48,4136.61 4106.48,4136.61 4156.48,4136.61 6021.5,4160.3 3698.53,4160.53 3956.48,4176.61 4006.48,4176.61 4056.48,4176.61 4106.48,4176.61 4156.48,4176.61 6376,4211 4006.48,4216.61 4056.48,4216.61 5966,4248.79 3708.13,4263.57 4450.55,4269.58 4468.6,4269.63 4486.66,4269.63 4505,4269.63 5976,4281 6048,4296 6008,4297.07 4032.88,4298.48 4419.28,4301.68 5877,4303 6214,4306 3410,4308 3425.72,4317.55 4419.28,4320.01 3399.44,4324.26 3415.6,4332.5 4419.28,4338.08 3399.92,4343.06 3432.13,4343.53 6055,4345 5983,4351.83 4419.22,4356.13 4024.98,4362.08 5876,4366 6001,4370 4450.5,4387.61 4468.84,4387.61 4486.9,4387.61 4504.95,4387.61 5982,4394.36 5876,4408 6003,4418 5861.1,4426 5876.87,4440 5982,4443.5 6028,4443.5 6080,4445 6017,4462 6060,4463.52 5893,4467 5982,4469.13 5958,4476.19 6036,4478 6005.28,4485.46 6131,4485.46 6185,4485 6234.83,4485.46 6432,4485 6080.02,4486.15 5902,4494.19 6016.12,4506.8 6041.93,4506.8 6067.73,4506.79 6093.53,4506.79 6119.33,4506.79 6145.13,4506.79 6170.93,4506.79 6196.73,4506.79 6222.53,4506.79 6248.33,4506.79 6274.14,4506.79 6299.94,4506.78 6325.74,4506.78 6351.54,4506.78 6377.34,4506.78 6403.14,4506.78 6428.94,4506.78 6002.62,4521.11 6028.42,4521.11 6054.22,4521.11 6080.02,4521.1 6105.82,4521.1 6131.62,4521.1 6157.43,4521.1 6183.23,4521.1 6209.03,4521.1 6234.83,4521.1 6260.63,4521.1 6286.43,4521.1 6312.23,4521.1 6338.03,4521.1 6363.83,4521.09 6389.64,4521.09 6415.44,4521.09 5895.62,4521.71 5885,4541 5902.89,4549.16 5924.43,4572.55 5899,4575 5863.91,4577 5955.13,4579.22 5974.27,4579.2 5993.41,4579.19 6451,4579 6018.42,4579.82 6044.22,4579.82 6070.02,4579.82 6095.82,4579.82 6121.62,4579.82 6147.43,4579.82 6173.23,4579.82 6199.03,4579.83 6224.83,4579.83 6250.63,4579.83 6276.43,4579.83 6302.23,4579.83 6328.03,4579.83 6353.83,4579.83 6379.64,4579.83 6405.44,4579.83 6431.24,4579.84
  other v2: 6109.37,3813.06 6287.97,3828.6 6086.73,3850.46 6132.01,3850.46 6266.32,3866 6309.62,3866 6109.37,3887.86 6287.97,3903.4 5781.96,4019.57 5831.57,4019.57 5881.17,4019.57 5740.03,4061.5 5781.96,4061.5 5831.57,4061.5 5881.17,4061.5 5923.1,4061.5 5740.03,4111.11 5781.96,4111.11 5831.57,4111.11 5881.17,4111.11 3382.36,4158.52 5740.03,4160.71 5781.96,4160.71 5831.57,4160.71 5881.17,4160.71 5781.96,4202.64 5831.57,4202.64 5881.17,4202.64 5482.58,4280.86 5445.17,4302.51 5519.98,4302.51 5482.58,4324.17
HD_AR_BSS_LOGGER: J2.43 RA2.7 | length 216.7
  Top Layer w5.5: v1(4559.93,4350.86) 4576.93,4350.86 4588.48,4362.41 RA2.7@4588.48,4413.17
  Bottom Layer w5.5: v1(4559.93,4350.86) 4559.93,4283.34 4570.82,4272.45 J2.43@4620.57,4272.45
HD_AR_CS1: J2.19 RA3.8 | length 314.3
  Top Layer w5.5: v1(4706.14,3859.2) 4706.14,3868.7 4722.1,3884.67 RA3.8@4749.31,3884.67
  Bottom Layer w5.5: J2.19@4620.57,4036.23 4685.35,4036.23 4711.7,4009.88 4711.7,3864.77 v1(4706.14,3859.2)
HD_AR_DMM_CLK: J2.10 R11.2 | length 93.9
  Bottom Layer w5.5: J2.10@4846.16,3937.81 4846.29,3937.94 R11.2@4940,3937.94
HD_AR_DMM_SYNC: J2.8 R10.2 | length 62
  Bottom Layer w5.5: J2.8@4846.16,3918.12 4904.12,3918.12 R10.2@4907,3921
HD_AR_DP0: J2.27 R88.2 | length 169.2
  Top Layer w5.5: v1(4706.93,4095.17) 4715.82,4086.28 4727.46,4086.28 4753.42,4060.33 R88.2@4767.16,4060.33
  Bottom Layer w5.5: J2.27@4620.57,4114.97 4671.25,4114.97 4675.76,4110.46 4691.64,4110.46 v1(4706.93,4095.17)
HD_AR_DP1: J2.29 R130.2 | length 310
  Top Layer w5.5: v1(4557.19,4143.31) 4605.78,4191.9 4605.78,4283.48 4617.95,4295.65 R130.2@4617.95,4361.13
  Bottom Layer w5.5: v1(4557.19,4143.31) 4565.84,4134.66 J2.29@4620.57,4134.66
HD_AR_DP2: J2.31 R132.2 | length 184.1
  Top Layer w5.5: v1(4708.21,4126.21) 4708.21,4122.45 4740.09,4090.57 R132.2@4766.31,4090.57
  Bottom Layer w5.5: J2.31@4620.57,4154.34 4696.66,4154.34 4708.21,4142.79 v1(4708.21,4126.21)
HD_AR_DP3: J2.33 R133.2 | length 140.6
  Top Layer w5.5: v1(4682.93,4176.03) 4682.93,4190.24 4720.33,4227.63 R133.2@4730.66,4227.63
  Bottom Layer w5.5: J2.33@4620.57,4174.03 4667.31,4174.03 4669.31,4176.03 v1(4682.93,4176.03)
HD_AR_DP4: J2.35 R135.2 | length 128.1
  Top Layer w5.5: v1(4705.93,4173.91) 4714.04,4182.01 R135.2@4714.04,4196.8
  Bottom Layer w5.5: J2.35@4620.57,4193.71 4621.21,4194.35 4698.76,4194.35 4705.93,4187.19 v1(4705.93,4173.91)
HD_AR_DP5: J2.37 R137.2 | length 459.2
  Top Layer w5.5: v1@4557.28,4174.75 4539.44,4156.91 4539.44,4097.34 4550.03,4086.75 4566.15,4086.75 4598.1,4054.8 4598.1,4039.08 4627.69,4009.49 4688.16,4009.49 4700.91,3996.73 4700.91,3955.09 R137.2@4681.54,3935.72
  Bottom Layer w5.5: v1(4558.03,4174) 4558.03,4198.13 4573.29,4213.4 J2.37@4620.57,4213.4
HD_AR_DP6: J2.39 R138.2 | length 158.1
  Top Layer w5.5: v1(4682.65,4241.56) 4703.85,4262.77 4720.85,4262.77 4742.55,4284.46 R138.2@4757.37,4284.46
  Bottom Layer w5.5: J2.39@4620.57,4233.08 4674.16,4233.08 v1(4682.65,4241.56)
HD_AR_DP7: J2.41 R140.2 | length 492.4
  Top Layer w5.5: v1(4557.19,4115.29) 4609.6,4062.88 4609.6,4043.84 4632.45,4020.99 4692.92,4020.99 4714.81,3999.1 R140.2@4714.81,3935.71
  Bottom Layer w5.5: v1(4557.19,4115.29) 4539.44,4133.04 4539.44,4229.07 4563.13,4252.77 J2.41@4620.57,4252.77
HD_AR_HOSTINTR1: J2.16 RA9.3 | length 96.7
  Bottom Layer w5.5: J2.16@4846.16,3996.86 4909.96,3996.86 4919.19,3987.64 RA9.3@4939.02,3987.64
HD_AR_MCUCLKOUT: J2.47 RA1.8 | length 304
  Top Layer w5.5: v1(4705.93,4292.02) 4714.77,4292.02 4726.28,4303.53 4726.28,4313.37 4756.21,4343.3 4756.21,4447.72 4756.3,4447.8 RA1.8@4756.3,4468.67
  Bottom Layer w5.5: J2.47@4620.57,4311.82 4699.4,4311.82 4705.93,4305.3 v1(4705.93,4292.02)
HD_AR_OSC_CLKOUT: J2.45 RA1.7 | length 274.3
  Top Layer w5.5: v1(4677.93,4292.14) 4677.93,4300.43 4691.13,4313.64 4710.28,4313.64 4744.5,4347.85 4744.5,4435.74 4740.55,4439.7 RA1.7@4740.55,4468.67
  Bottom Layer w5.5: J2.45@4620.57,4292.14 v1(4677.93,4292.14)
HD_AR_PMIC_CLKOUT_SOP2: J2.49 RA1.5 | length 216
  Top Layer w5.5: v1(4677.93,4334.51) 4721.5,4378.08 4721.5,4426.22 4711.5,4436.22 4711.5,4455.32 4709.05,4457.77 RA1.5@4709.05,4468.67
  Bottom Layer w5.5: J2.49@4620.57,4331.51 4623.57,4334.51 v1(4677.93,4334.51)
HD_AR_SCL: J2.55 RA2.5 | length 144.3
  Top Layer w5.5: v1(4539.66,4372.53) 4539.66,4388.23 4556.98,4405.56 RA2.5@4556.98,4413.17
  Bottom Layer w5.5: v1(4539.66,4372.53) 4539.66,4384.9 4546.38,4391.63 4619.5,4391.63 J2.55@4620.57,4390.56
HD_AR_SDA: J2.53 RA2.6 | length 101.8
  Top Layer w5.5: v1(4563.2,4373.88) 4563.2,4390.63 4572.73,4400.16 RA2.6@4572.73,4413.17
  Bottom Layer w5.5: v1(4563.2,4373.88) 4566.2,4370.88 J2.53@4620.57,4370.88
HD_AR_TCK: J2.15 RA4.7 | length 164.6
  Top Layer w5.5: v1(4552.59,4003.26) 4569.09,4003.26 4576.29,4010.46 4592.85,4010.46 4613.18,3990.14 4613.18,3968.8 RA4.7@4612.69,3968.32
  Bottom Layer w5.5: v1(4552.59,4003.26) 4558.99,3996.86 J2.15@4620.57,3996.86
HD_AR_TDI: J2.11 RA4.5 | length 102.8
  Top Layer w5.5: RA4.5@4644.19,3968.32 4678.62,3968.32 v1(4681.54,3965.4)
  Bottom Layer w5.5: J2.11@4620.57,3957.49 4671.42,3957.49 4673.64,3957.49 v1(4681.54,3965.4)
HD_AR_TDO_SOP0: J2.17 RA4.6 | length 155.4
  Top Layer w5.5: RA4.6@4628.44,3968.32 4628.44,3984.53 4633.29,3989.38 v1(4683.16,3989.38)
  Bottom Layer w5.5: J2.17@4620.57,4016.55 4670.75,4016.55 4683.16,4004.13 v1(4683.16,3989.38)
HD_AR_TMS: J2.13 RA4.8 | length 146.7
  Top Layer w5.5: v1(4551.95,3978.41) 4559.05,3985.51 4573.47,3985.51 4585.23,3997.26 4589.79,3997.26 4596.94,3990.11 RA4.8@4596.94,3968.32
  Bottom Layer w5.5: v1(4551.95,3978.41) 4619.34,3978.41 J2.13@4620.57,3977.18
HD_AR_WARMRST: J2.51 RA1.6 | length 251.7
  Top Layer w5.5: v1(4705.93,4334.39) 4733,4361.46 4733,4430.98 4724.8,4439.18 RA1.6@4724.8,4468.67
  Bottom Layer w5.5: J2.51@4620.57,4351.19 4666.81,4351.19 4672.24,4356.63 4693.97,4356.63 4705.93,4344.67 v1(4705.93,4334.39)
HD_SPI_CLK1: J2.21 RA3.7 | length 396.4
  Top Layer w5.5: v1(4679.93,4055.92) 4668.47,4067.38 4628.14,4067.38 4621.38,4060.62 4621.38,4048.32 4637.22,4032.49 4697.69,4032.49 4733.08,3997.1 4733.08,3926.57 4765.06,3894.59 RA3.7@4765.06,3884.67
  Bottom Layer w5.5: J2.21@4620.57,4055.92 v1(4679.93,4055.92)
HD_SPI_MISO1: J2.25 RA3.5 | length 325.8
  Top Layer w5.5: v1(4683.12,4092.71) 4701.05,4074.78 4713.3,4074.78 4756.08,4032.01 4756.08,3936.1 4796.56,3895.62 RA3.5@4796.56,3884.67
  Bottom Layer w5.5: J2.25@4620.57,4095.29 4623.14,4092.71 v1(4683.12,4092.71)
HD_SPI_MOSI1: J2.23 RA3.6 | length 295.7
  Top Layer w5.5: v1(4705.93,4055.8) 4744.58,4017.15 4744.58,3931.34 4780.81,3895.1 RA3.6@4780.81,3884.67
  Bottom Layer w5.5: J2.23@4620.57,4075.6 4670.79,4075.6 4672.47,4073.92 4687.81,4073.92 v1(4705.93,4055.8)
INTN: R95.1 TP46.1 U10.11 | length 138.2
  Bottom Layer w5.5: TP46.1@5159.8,4472.11 5169.45,4462.46 5223.59,4462.46 5232.68,4453.37 R95.1@5232.68,4444.39 ; R95.1@5233.19,4444.39 5244.43,4444.39 5257.65,4457.6 U10.11@5276.29,4457.6
JTAG_TCK: J7.4 U8.25 | length 555.3
  Top Layer w5.5: v1(5684.62,3977.5) 5723.05,3977.5 U8.25@5723.3,3977.25
  Sig2 w4.2: v1(5684.62,3977.5) 5707.06,3999.94 5707.06,4312.86 5686.47,4333.46 J7.4@5686.47,4476.19
JTAG_TDI: J7.8 R113.1 U8.27 | length 1196.3
  Top Layer w5.5: R113.1@5258.37,4455.49 5314.86,4455.49 5372.59,4397.76 5617.31,4397.76 5659.55,4440 5750.28,4440 J7.8@5786.47,4476.19 ; U8.27@5762.67,3977.25 5762.67,3958.37 v1(5774.37,3946.67)
  Sig2 w4.2: v1(5774.37,3946.67) 5723.89,3997.15 5723.89,4377.98 5747.37,4401.46 5747.37,4437.09 J7.8@5786.47,4476.19
JTAG_TDO: J7.6 U8.26 | length 575.8
  Top Layer w5.5: v1(5737.37,3949.46) 5742.99,3955.08 U8.26@5742.99,3977.25
  Sig2 w4.2: J7.6@5736.47,4476.19 5736.47,4404.98 5715.49,4384.01 5715.49,3969.34 5735.37,3949.46 v1(5737.37,3949.46)
JTAG_TMS: J7.2 U8.24 | length 533.9
  Top Layer w5.5: v1(5673.78,4002.46) 5673.97,4002.65 5697.52,4002.65 U8.24@5697.71,4002.84
  Sig2 w4.2: J7.2@5636.47,4476.19 5636.47,4371.58 5698.66,4309.38 5698.66,4029 5673.78,4004.12 v1(5673.78,4002.46)
MRDY: TP16.1 U8.21 | length 81.4
  Top Layer w5.5: TP16.1@5629.37,4093.46 5643.37,4093.46 5674.94,4061.9 U8.21@5697.71,4061.9
NetA1_4: A1.4 C99.1 C104.1 | length 143.8
  Top Layer w12: C99.1@6348.66,4550.46 6430.41,4550.46 A1.4@6492.49,4550.46
NetC8_1: C8.1 U4.4 | length 99.9
  Bottom Layer w5.5: C8.1@6401.4,3719.01 6415.01,3719.01 6420.75,3724.75 6420.75,3759.35 6407.77,3772.33 U4.4@6407.77,3797.49
NetC13_2: C13.2 U7.9 | length 78.7
  Bottom Layer w5.5: C13.2@5237.19,4028.9 5248.88,4028.9 5256.01,4021.77 5256.01,4001.61 5265.35,3992.27 U7.9@5265.35,3968.74
NetC21_2: C21.2 L1.2 | length 34.8
  Top Layer w12: L1.2@5994.11,4324.41 C21.2@6028.92,4324.41
NetC22_1: C22.1 L6.2 L9.1 | length 125.1
  Top Layer w12: L6.2@5903.37,4415.16 5903.37,4439.99 L9.1@5930.04,4466.65 5956.7,4439.99 C22.1@5956.7,4415.16
NetC24_1: C24.1 U8.23 | length 65.2
  Top Layer w5.5: C24.1@5640.38,4003.46 5642.33,4003.46 5661.39,4022.52 U8.23@5697.71,4022.52
NetC41_1: C41.1 L9.2 L10.1 | length 168.6
  Top Layer w12: L9.2@5930.04,4504.05 5930.04,4515.5 cw(c5965,4515.5) 5965,4550.46 C41.1@5975.28,4550.46 5995.28,4550.46 L10.1@6067.28,4550.46
NetC43_2: C43.2 FL12.1 U12.3 | length 65.8
  Bottom Layer w10: FL12.1@5469.78,4210.46 5475.18,4210.46 5477.31,4212.59 C43.2@5497.81,4212.59
  Bottom Layer w12: FL12.1@5469.78,4210.46 U12.3@5469.78,4247.39
NetC93_1: C93.1 C99.2 | length 83.6
  Top Layer w12: C93.1@6225.66,4550.46 C99.2@6309.29,4550.46
NetC93_2: C93.2 L10.2 | length 81.6
  Top Layer w12: L10.2@6104.68,4550.46 C93.2@6186.29,4550.46
NetC106_2: C106.2 R119.1 R126.2 | length 341.8
  Sig1 w10: v1(5433.56,4476.78) 5494.34,4416 v1(5609,4416)
  Bottom Layer w10: R126.2@5425.41,4410.54 5425.41,4468.62 v1(5433.56,4476.78) ; R119.1@5539.74,4410.82 C106.2@5574,4410.82 5604.03,4410.82 5609,4415.79 v1(5609,4416)
NetC108_2: C108.2 FL3.1 U17.3 | length 78.1
  Top Layer w10: FL3.1@6156,3855.69 6156.31,3856 C108.2@6197.97,3856 6207.97,3856 6210.76,3853.2 U17.3@6232.85,3853.2
NetC110_2: C110.2 R114.1 R117.2 | length 224.3
  Top Layer w4: R114.1@6397.76,3928.98 6398.78,3930 v1(6433,3930) ; R117.2@6397.85,3803.83 6405.69,3795.99 6437.31,3795.99 C110.2@6440,3793.3 ; v1(6435.31,3826.69) 6440.7,3821.3 6440.7,3794 C110.2@6440,3793.3 ; C110.2@6440,3795.27 C110.2@6440,3793.3
  Sig2 w4.2: v1(6433,3930) 6433,3829 v1(6435.31,3826.69)
NetD1_2: D1.2 FL2.2
NetD2_2: D2.2 FL11.2
NetJ2_12: J2.12 RA9.1 | length 93.4
  Bottom Layer w5.5: J2.12@4846.16,3957.49 4914.14,3957.49 4915.49,3956.14 RA9.1@4939.02,3956.14
NetJ2_14: J2.14 RA9.2 | length 95.1
  Bottom Layer w5.5: J2.14@4846.16,3977.18 4913.28,3977.18 4918.58,3971.89 RA9.2@4939.02,3971.89
NetJ2_18: J2.18 RA9.4 | length 98.3
  Bottom Layer w5.5: J2.18@4846.16,4016.55 4917.47,4016.55 4930.63,4003.38 RA9.4@4939.02,4003.38
NetJ2_22: J2.22 RA8.1 | length 91.6
  Bottom Layer w5.5: J2.22@4846.16,4055.92 4903.41,4055.92 4919.74,4072.25 RA8.1@4931.04,4072.25
NetJ2_24: J2.24 RA8.2 | length 90
  Bottom Layer w5.5: J2.24@4846.16,4075.6 4899.11,4075.6 4911.5,4088 RA8.2@4931.04,4088
NetJ2_28: J2.28 RA8.3 | length 91.9
  Bottom Layer w4: J2.28@4846.16,4114.97 4849.05,4117.87 4900.55,4117.87 4913.13,4105.29 4929.5,4105.29 RA8.3@4931.04,4103.74
NetJ2_30: J2.30 RA8.4 | length 93.8
  Bottom Layer w4: J2.30@4846.16,4134.66 4886.03,4134.66 4891.82,4128.87 4905.1,4128.87 4917.68,4116.29 4927.83,4116.29 RA8.4@4931.04,4119.49
NetJ2_34: J2.34 RA7.1 | length 94.1
  Bottom Layer w4: J2.34@4846.16,4174.03 4892.84,4174.03 4897.18,4178.37 4906.52,4178.37 4920.55,4192.4 4929.32,4192.4 RA7.1@4931.69,4190.03
NetJ2_36: J2.36 RA7.2 | length 94.1
  Bottom Layer w4: J2.36@4846.16,4193.71 4892.84,4193.71 4897.18,4189.37 4901.96,4189.37 4916,4203.4 4929.32,4203.4 RA7.2@4931.69,4205.78
NetJ2_40: J2.40 RA7.3 | length 93.3
  Bottom Layer w4: J2.40@4846.16,4233.08 4892.84,4233.08 4896.4,4236.64 4909.94,4236.64 4919.3,4227.27 4923.48,4227.27 4929.23,4221.53 RA7.3@4931.69,4221.53
NetJ2_42: J2.42 RA7.4 | length 92
  Bottom Layer w4: J2.42@4846.16,4252.77 4892.84,4252.77 4898.97,4246.64 4915.49,4246.64 4924.86,4237.27 RA7.4@4931.69,4237.27
NetJ2_46: J2.46 RA6.1 | length 90.9
  Bottom Layer w4: J2.46@4846.16,4292.14 4892.84,4292.14 4897.18,4296.48 4904.46,4296.48 4914.12,4306.15 4919.89,4306.15 4922.26,4303.77 RA6.1@4930.26,4303.77
NetJ2_48: J2.48 RA6.2 | length 90.9
  Bottom Layer w4: J2.48@4846.16,4311.82 4892.84,4311.82 4897.18,4307.48 4899.9,4307.48 4903.44,4311.02 4909.57,4317.15 4919.89,4317.15 4922.26,4319.52 RA6.2@4930.26,4319.52
NetJ2_52: J2.52 RA6.3 | length 90.7
  Bottom Layer w5.5: J2.52@4846.16,4351.19 4897.66,4351.19 4913.58,4335.27 RA6.3@4930.26,4335.27
NetJ2_54: J2.54 RA6.4 | length 92.3
  Bottom Layer w5.5: J2.54@4846.16,4370.88 4899.09,4370.88 4918.95,4351.02 RA6.4@4930.26,4351.02
NetJ2_56: J2.56 RA5.1 | length 92.2
  Bottom Layer w5.5: J2.56@4846.16,4390.56 4899.25,4390.56 4917.78,4409.09 RA5.1@4930.68,4409.09
NetJ2_57: J2.57 R14.1 | length 428.2
  Top Layer w5.5: v1(4831,4471.63) 4831,4488.23 4836.24,4493.46 R14.1@4886,4493.46
  Bottom Layer w5.5: J2.57@4620.57,4410.25 4669.54,4410.25 4678.95,4400.84 4693.94,4400.84 4711.09,4417.99 4711.09,4516 4723.3,4528.21 4785.55,4528.21 4831,4482.76 v1(4831,4471.63)
NetJ2_58: J2.58 RA5.2 | length 90.6
  Bottom Layer w5.5: J2.58@4846.16,4410.25 4901.51,4410.25 4916.1,4424.84 RA5.2@4930.68,4424.84
NetJ2_59: J2.59 R12.1 | length 505.4
  Bottom Layer w5.5: J2.59@4620.57,4429.93 4579.07,4429.93 4575,4434 4575,4491 4649.45,4565.45 4690.36,4565.45 4713.81,4542 4788.02,4542 4834.56,4495.46 R12.1@4916.37,4495.46
NetJ2_60: J2.60 RA5.3 | length 88.9
  Bottom Layer w5.5: J2.60@4846.16,4429.93 4901.9,4429.93 4912.56,4440.59 RA5.3@4930.68,4440.59
NetJ4_1: J4.1 R185.2 | length 1327.2
  Top Layer w5.5: J4.1@4655.33,4261.92 4686.74,4261.92 4699.09,4274.27 4713.5,4274.27 4751.62,4312.39 v1(4756.43,4312.39) ; v1(5497.37,3826.46) 5497.37,3844.68 5511.35,3858.66 R185.2@5511.35,3882.46
  Sig2 w4.2: v1(4756.43,4312.39) 4981.45,4312.38 5020.9,4351.83 5040.54,4351.83 5113.56,4278.81 5113.56,4154.64 5283.07,3985.13 5283.07,3862.02 5347.22,3797.87 5468.78,3797.87 v1(5497.37,3826.46)
NetJ4_2: J4.2 R184.2 | length 1631.1
  Top Layer w5.5: J4.2@4655.33,4242.23 4634.63,4242.23 4630.69,4246.17 4630.69,4275.86 4660.18,4305.35 4660.18,4341.86 4710,4391.68 4710,4421.45 4700,4431.45 4700,4450.56 v1(4690.34,4460.22) ; v1@5545.1,3923.87 5562.38,3906.59 R184.2@5562.38,3894.8
  Sig2 w4.2: v1(4690.34,4460.22) 4709.52,4441.04 4966.8,4441.04 4966.98,4440.86 4975.27,4440.86 5131.15,4284.99 5131.15,4160.82 5299.87,3992.09 5299.87,3868.98 5351.58,3817.27 5443.23,3817.27 5545.6,3919.63 v1(5545.6,3924.37)
NetJ4_3: J4.3 R183.2 | length 1602.8
  Top Layer w5.5: J4.3@4655.33,4222.55 4690.14,4222.55 v1(4709.72,4242.13) ; v1(5575.84,3921.94) 5593.19,3904.59 R183.2@5593.19,3895.87
  Sig2 w4.2: v1(4709.72,4242.13) 4726.14,4242.13 4742.4,4258.39 4742.4,4258.61 4786.62,4302.83 4983.78,4302.83 5024.38,4343.43 5037.06,4343.43 5105.16,4275.33 5105.16,4151.16 5274.67,3981.65 5274.67,3858.54 5345.04,3788.17 5489.57,3788.17 5489.82,3788.41 5631.72,3788.41 5645.37,3802.06 5645.37,3852.41 v1(5575.84,3921.94)
NetJ4_5: J4.5 R182.2 | length 220.1
  Top Layer w5.5: R182.2@4650.14,4360.81 4648.68,4359.35 4648.68,4310.11 4619.19,4280.63 4619.19,4194.32 4630.34,4183.18 J4.5@4655.33,4183.18
NetJ8_1: J8.1 R126.1 U12.6 | length 219.8
  Bottom Layer w4: J8.1@5409.37,4535.46 5454.32,4490.51 5454.32,4467.02 5477.53,4443.82 5477.53,4423.28 R126.1@5464.78,4410.54 5477.53,4397.79 5477.53,4380.36 5469.78,4372.61 U12.6@5469.78,4357.63
NetJ8_3: J8.3 R119.2 U12.7 | length 219.8
  Bottom Layer w4: U12.7@5495.37,4357.63 5495.37,4371.72 5487.63,4379.47 5487.63,4398.08 R119.2@5500.37,4410.82 5487.63,4423.57 5487.63,4448 5464.42,4471.2 5464.42,4490.51 J8.3@5509.37,4535.46
NetJ9_1: J9.1 R109.2 | length 2240.7
  Top Layer w5.5: R109.2@3744.93,4012.38 3754.32,4003 3759.5,4003 3763.64,3998.86 3763.64,3993.5 v1(3773.02,3984.13) ; v1(5117.78,4372) 5117.78,4347.88 5104,4334.1 5104,4267.56 5146.39,4225.17 5232.96,4225.17 J9.1@5232.96,4223.56
  Sig1 w4.2: v1(3773.02,3984.13) 3789.15,3968 3897.5,3968 3913.75,3984.25 3944.25,3984.25 3982.78,4022.78 3982.78,4213.56 4000.43,4231.21 4148.66,4231.21 4179.85,4200.02 4204.85,4200.02 4243.61,4238.78 4285.29,4238.78 ; 4285.46,4238.89 4291.67,4245.1 4294.06,4245.1 4405.1,4245.1 4414.28,4254.28 4512.93,4254.28 4593,4334.35 4593,4467 4614,4488 4630,4488 4678.8,4439.2 4911.5,4439.2 4961.3,4489 5098.57,4489 5131,4456.57 5131,4385.22 v1(5117.78,4372)
NetJ10_1: J10.1 R117.1 U17.6 | length 279.7
  Top Layer w4: U17.6@6343.09,3853.2 6356.9,3853.2 6364.64,3860.95 6380.11,3860.95 R117.1@6397.85,3843.2 6416.47,3861.82 6444.8,3861.82 6467.6,3839.02 6467.6,3813.1 6485.75,3794.95 6498.05,3794.95 J10.1@6543,3750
